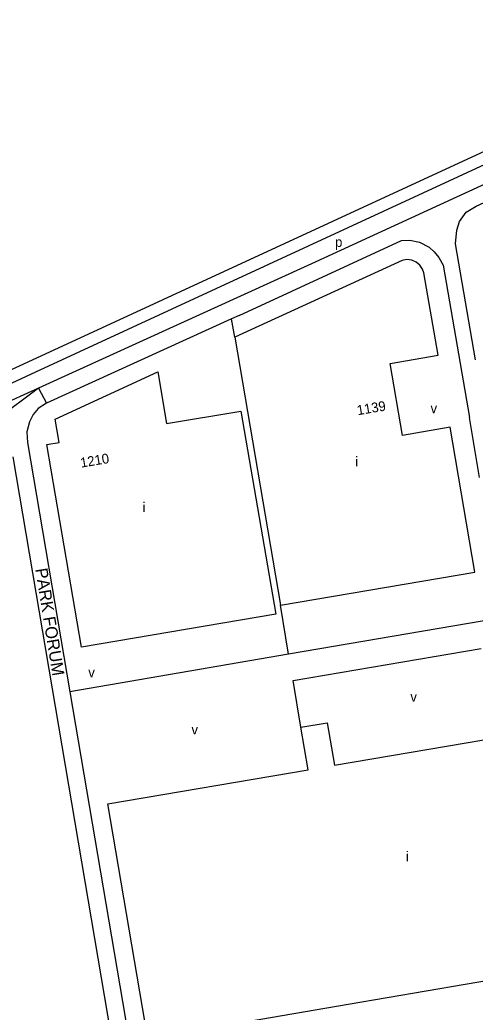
# Model space of a CAD drawing. Extents: x 154320 to 156262, y 382651 to 384180.
# Drawn here: x 154681.1 to 154867.6, y 383508.4 to 383914.5 of the extents above; entities that cross this region are included whole.
import ezdxf

# ---------------------------------------------------------------- set-up
doc = ezdxf.new("R2010")
doc.units = 0
for name, color, linetype in [('BLT_Basislijn', 7, 'Continuous'), ('BLT_Bebouwing', 7, 'Continuous'), ('BLT_Centroide', 7, 'Continuous'), ('BLT_Huisnummer', 7, 'Continuous'), ('BLT_Straatnaam', 7, 'Continuous'), ('BLT_Vlakafsluiter', 7, 'Continuous')]:
    doc.layers.add(name, color=color, linetype=linetype)

msp = doc.modelspace()

# ---------------------------------------------------------------- linework, layer by layer
at = {"layer": 'BLT_Basislijn'}
for p, q in [((154999.09, 383919.62), (154635.38, 383751.76)), ((154967.99, 383899.76), (154799.24, 383821.88)), ((154963.08, 383889.18), (154800.65, 383814.69)), ((154770.99, 383793.51), (154837.51, 383824.13)), ((154799.24, 383821.88), (154687.54, 383770.33)), ((154854.49, 383814.06), (154865.28, 383751.73)), ((154769.16, 383784.68), (154767.9, 383792.1)), ((154687.54, 383770.33), (154655.62, 383755.6)), ((154688.72, 383763.76), (154593.48, 383720.42)), ((154869.35, 383727.19), (154865.28, 383751.73)), ((154678.23, 383735.59), (154732.83, 383414.64)), ((154791.23, 383654.83), (154787.88, 383674.89)), ((154879.13, 383669.91), (154791.23, 383654.83)), ((154791.23, 383654.83), (154701.68, 383639.46)), ((154701.68, 383639.46), (154727.82, 383485.81))]:
    msp.add_line(p, q, dxfattribs=at)
for points in [[(154867.71, 383775.29), (154859.63, 383822.86), (154860.09, 383828.4), (154861.2, 383832), (154863.96, 383835.74), (154868.05, 383838.28), (154913.4, 383859.08)], [(154837.51, 383824.13), (154840.88, 383824.34), (154844.85, 383823.48), (154848.73, 383821.4), (154850.79, 383819.57), (154852.78, 383817.21), (154854.49, 383814.06)], [(154800.65, 383814.69), (154688.72, 383763.76)], [(154767.9, 383792.1), (154692.05, 383757.58)], [(154770.99, 383793.51), (154767.9, 383792.1)], [(154692.05, 383757.58), (154688.64, 383755.43), (154686.61, 383752.98), (154685.04, 383750), (154684.04, 383745.89), (154684.32, 383741.54), (154701.68, 383639.46)], [(154793.03, 383644.07), (154870.05, 383657.16)], [(154796.3, 383624.97), (154793.03, 383644.07)]]:
    msp.add_lwpolyline(points, dxfattribs=at)
at = {"layer": 'BLT_Bebouwing'}
msp.add_line((154815.63, 383511.49), (154738.94, 383498.44), dxfattribs=at)
for points in [[(154787.88, 383674.89), (154867.57, 383688.39), (154857.46, 383747.73), (154837.88, 383744.34), (154832.77, 383773.85), (154852.43, 383777.26), (154846.65, 383810.94), (154846.13, 383812.49), (154845.04, 383814.16), (154843.44, 383815.35), (154841.73, 383816.14), (154839.45, 383816.45), (154837.74, 383816.06), (154769.16, 383784.68)], [(154769.16, 383784.68), (154787.88, 383674.89)], [(154738.94, 383498.44), (154733.53, 383497.52), (154717.21, 383593.64), (154799.26, 383607.57), (154796.3, 383624.97)], [(154796.3, 383624.97), (154807.03, 383626.73), (154809.97, 383609.47), (154879.18, 383621.21)], [(154895.55, 383525.11), (154815.63, 383511.49)]]:
    msp.add_lwpolyline(points, dxfattribs=at)
msp.add_lwpolyline([(154695.64, 383751.1), (154737.69, 383770.39), (154741.27, 383749.25), (154771.65, 383754.41), (154786.02, 383671.23), (154706.36, 383657.7), (154692.24, 383740.69), (154697.27, 383741.55)], close=True, dxfattribs=at)
at = {"layer": 'BLT_Vlakafsluiter'}
for q in [(154662.39, 383744.08), (154692.05, 383757.58)]:
    msp.add_line((154688.72, 383763.76), q, dxfattribs=at)

# ---------------------------------------------------------------- texts
at = {"layer": 'BLT_Centroide'}
for s, p in [('p', (154810.27, 383821.57)), ('i', (154818.48, 383731.72)), ('i', (154731.42, 383713.05)), ('i', (154839.28, 383570.18))]:
    msp.add_text(s, height=4, dxfattribs=at).set_placement(p)
for p in [(154849.34, 383753.53), (154709.16, 383645.46), (154841.09, 383635.46), (154751.42, 383622.06)]:
    msp.add_text('v', height=4, rotation=359.5, dxfattribs=at).set_placement(p)
at = {"layer": 'BLT_Huisnummer'}
for s, p in [('1139', (154819.56, 383752.67)), ('1210', (154706.24, 383731.2))]:
    msp.add_text(s, height=4, rotation=9.6197, dxfattribs=at).set_placement(p)
at = {"layer": 'BLT_Straatnaam'}
msp.add_text('PARK FORUM', height=5, rotation=279.1888, dxfattribs=at).set_placement((154687.42, 383689.73))

doc.saveas('drawing.dxf')
